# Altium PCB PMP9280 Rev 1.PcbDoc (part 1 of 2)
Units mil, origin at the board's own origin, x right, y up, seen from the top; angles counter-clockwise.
Board outline 4050 x 2360 mil, 4 copper layers (Top Layer, MidLayer1, MidLayer2, Bottom Layer), stack 61.2 mil thick; 80 components, 27 nets, 139 pads, 275 vias.
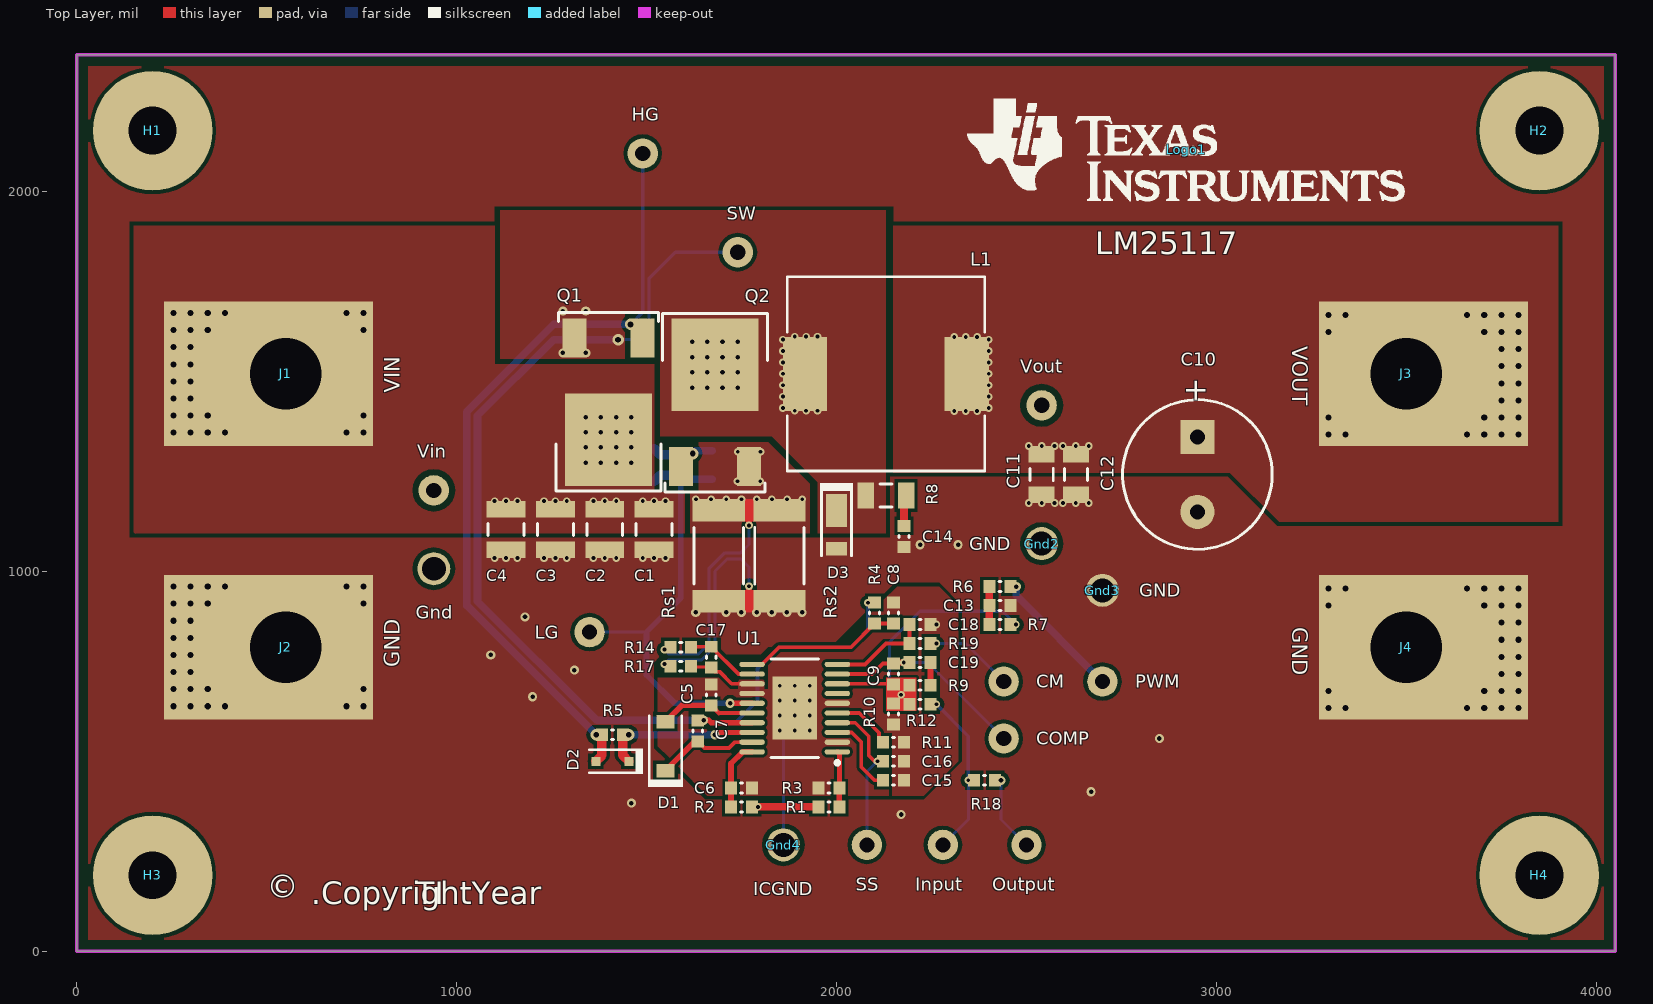
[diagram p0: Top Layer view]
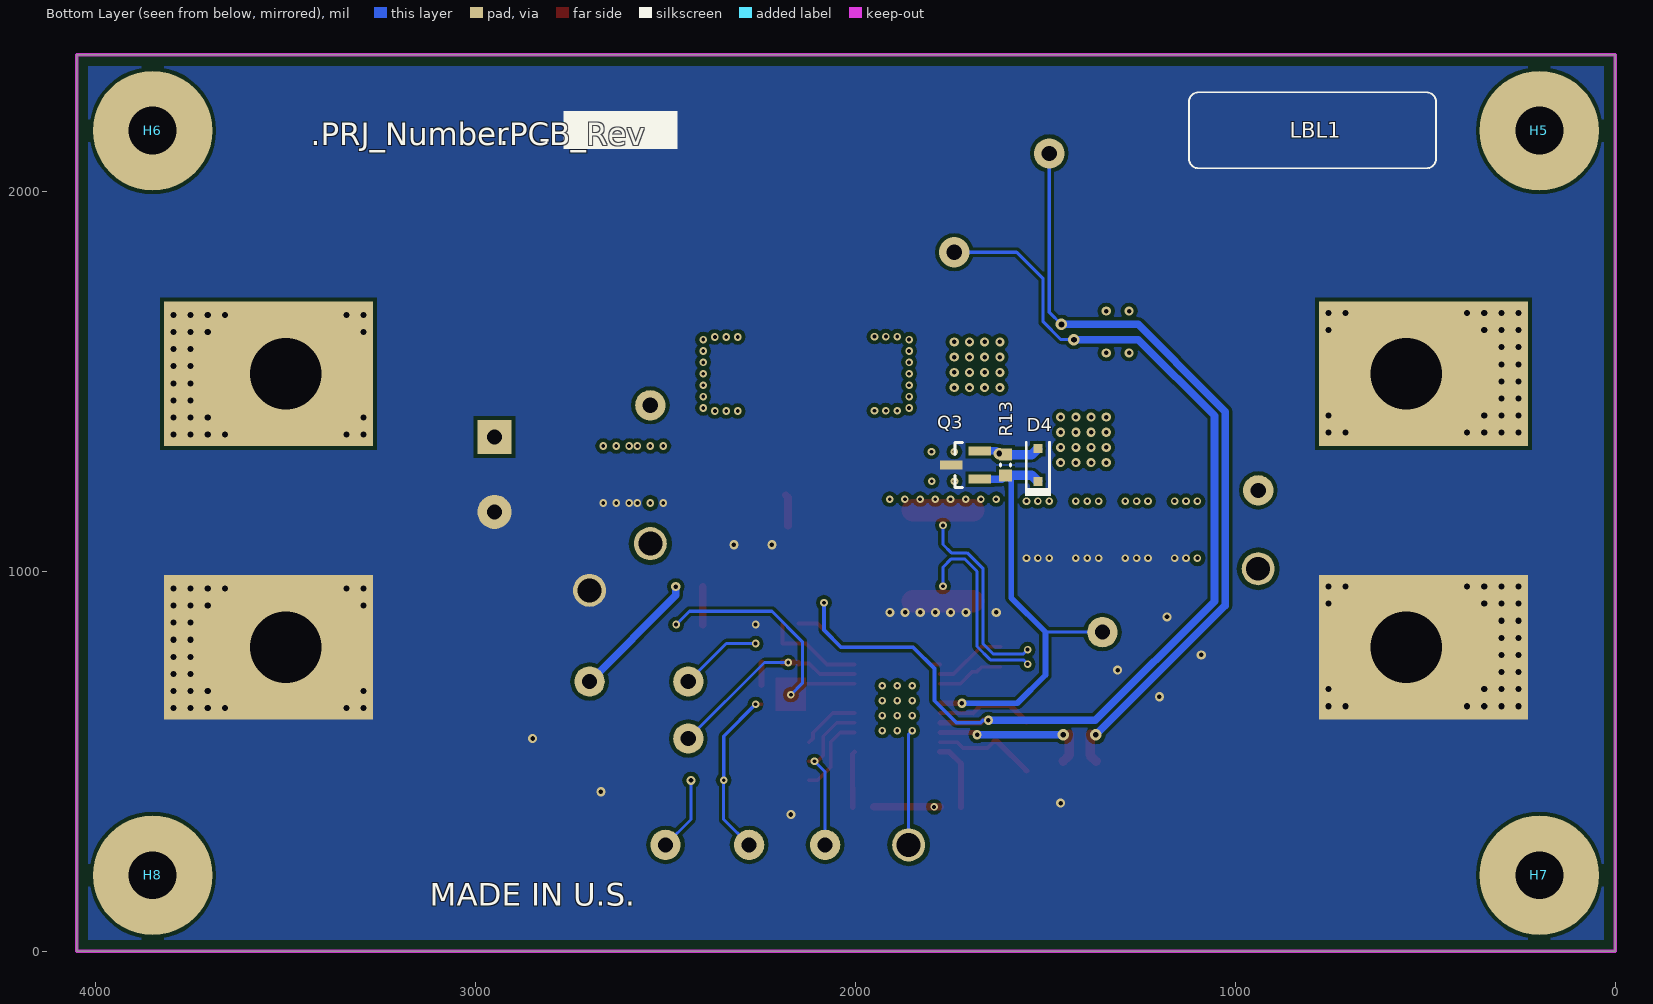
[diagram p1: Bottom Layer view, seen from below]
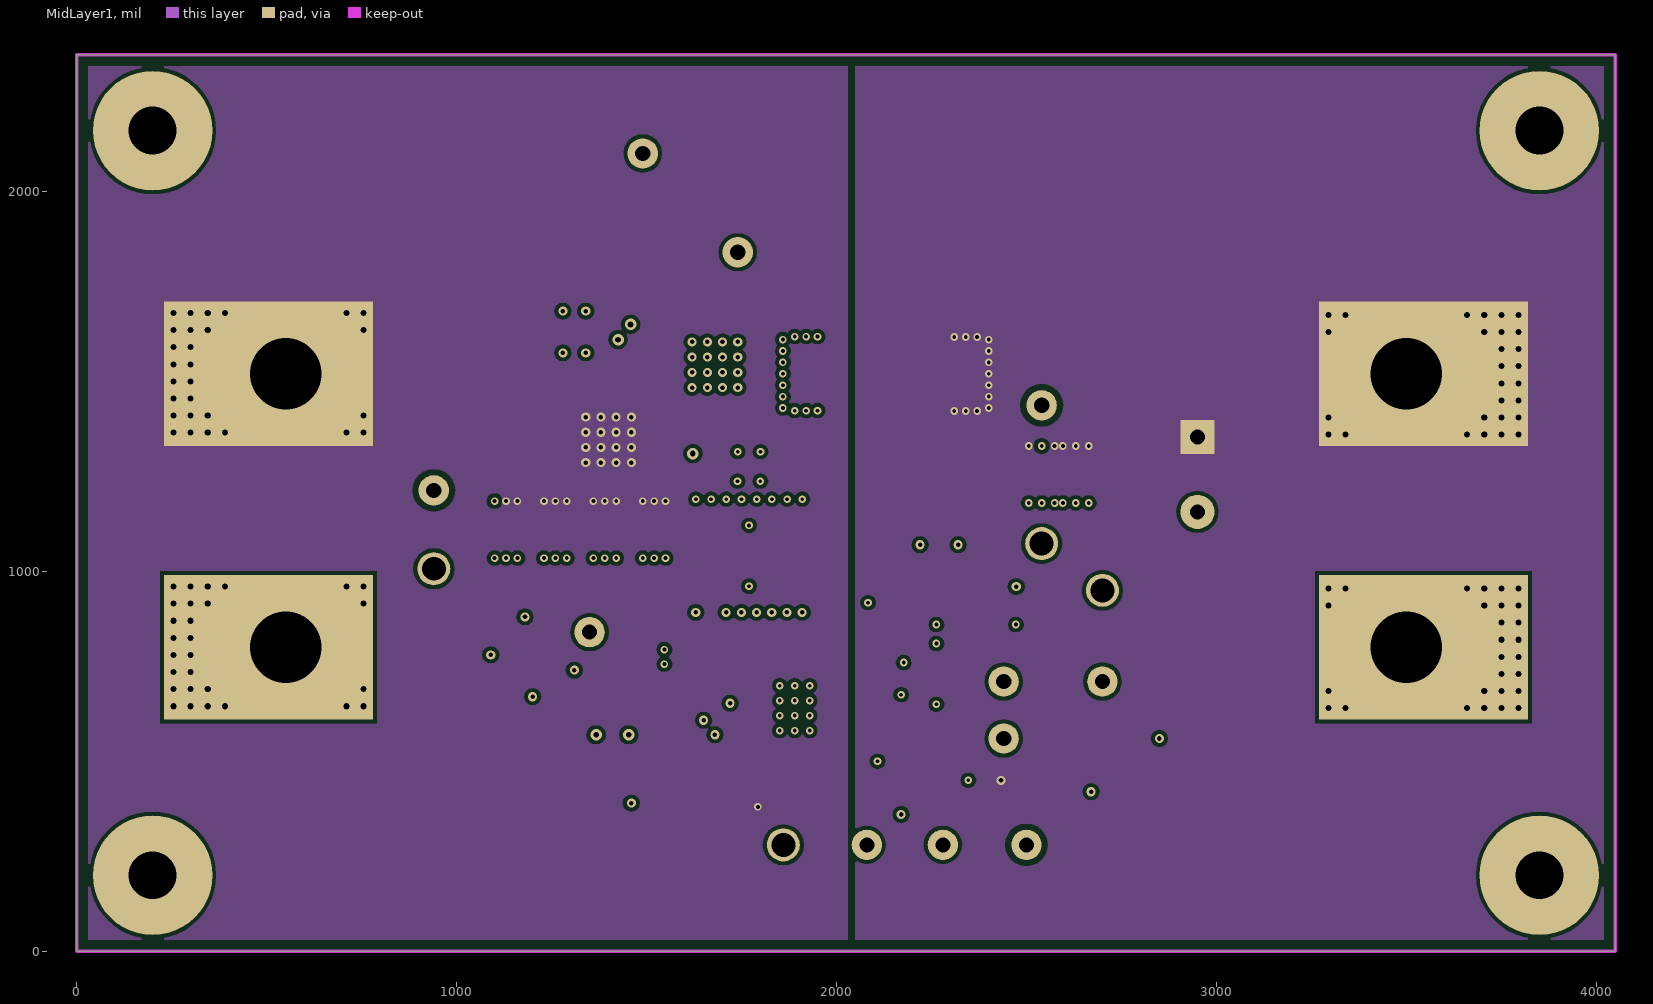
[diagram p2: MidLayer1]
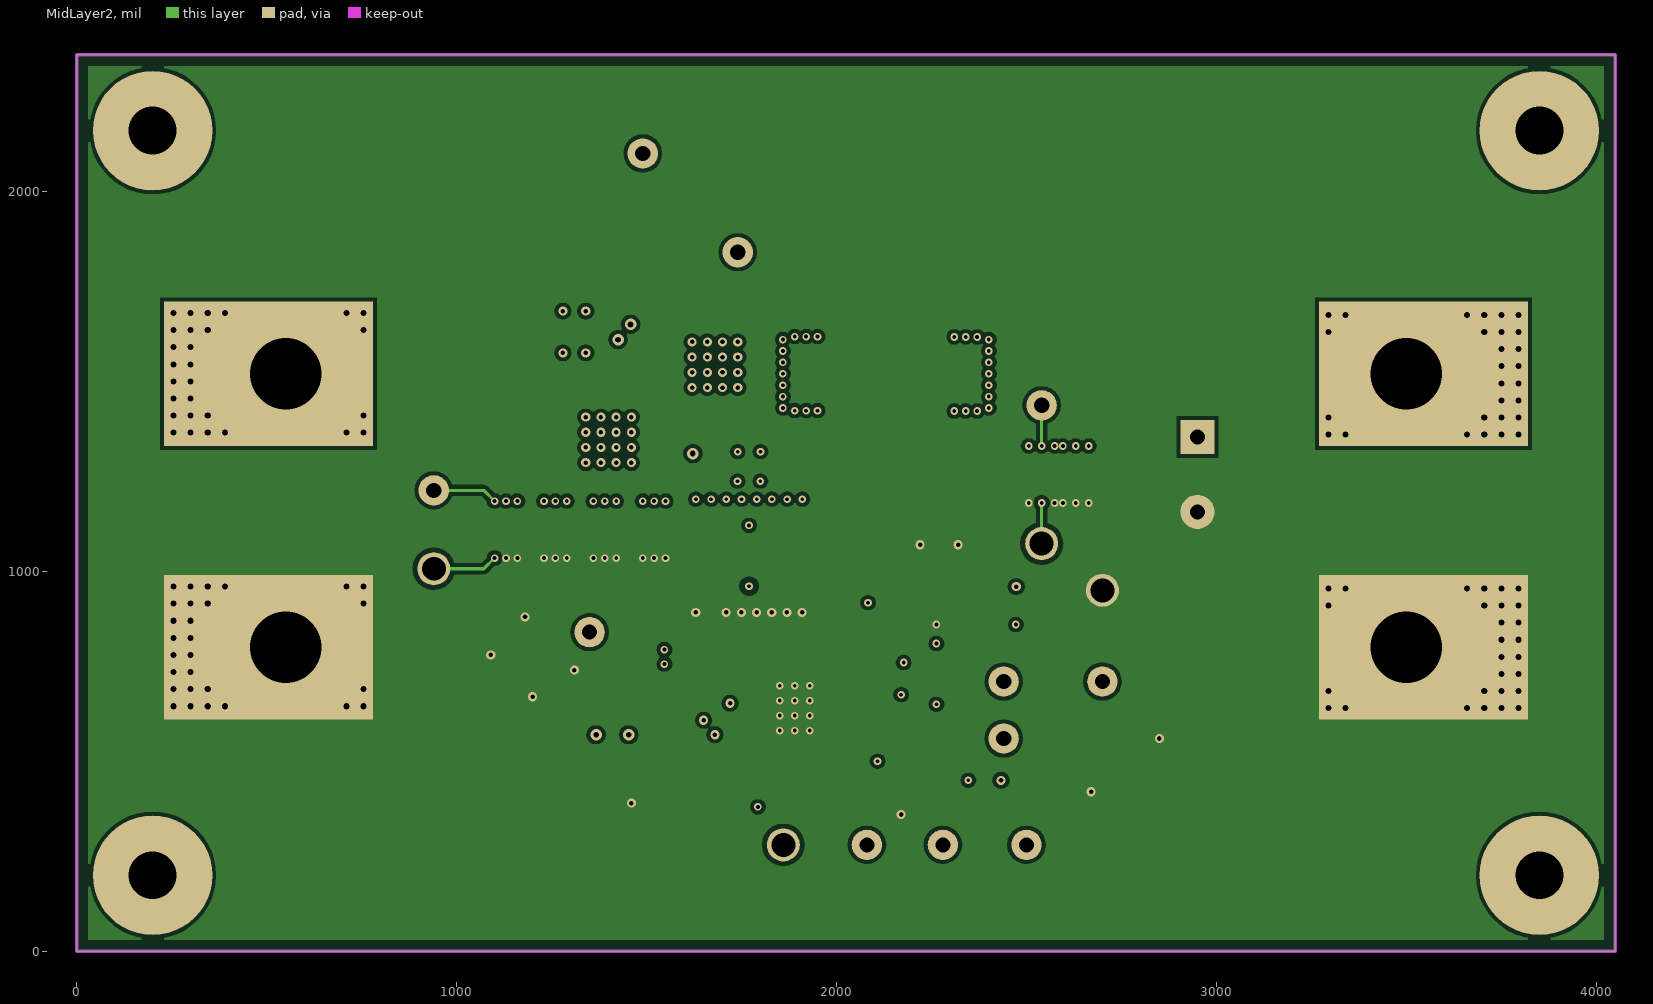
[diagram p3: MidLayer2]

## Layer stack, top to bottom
Top Solder: solder mask 0.4, Solder Resist, Dk 3.5
Top Layer: signal copper 1.4
Dielectric1: core 12.6, FR-4, Dk 4.8
MidLayer1: signal copper 1.4
Dielectric2: prepreg 30.4, FR-4, Dk 4.8
MidLayer2: signal copper 1.4
Dielectric3: core 12.6, FR-4, Dk 4.8
Bottom Layer: signal copper 1.4
Bottom Solder: solder mask 0.4, Solder Resist, Dk 3.5

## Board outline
0,0 0,2360 4050,2360 4050,0

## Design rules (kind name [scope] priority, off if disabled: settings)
AcuteAngle [All] p1: minimum=4.50000000000000E+0001 checktracksonly=FALSE
AssemblyTestPointUsage [All] p1: valid=2
Clearance Clearance_Poly_1 [InNet('GND') vs OnLayer('Top Layer')] p1: gap=8 ignorepadtopadclearanceinfootprint=FALSE except(0: Arc-Hole Track-Hole SMDPad-Hole THPad-Hole Via-Hole Fill-Hole Poly-Hole Region-Hole Text-Hole)
Clearance Clearance_Poly_2 [InNet('GND') vs OnLayer('Bottom Layer')] p2: gap=8 ignorepadtopadclearanceinfootprint=FALSE except(0: Arc-Hole Track-Hole SMDPad-Hole THPad-Hole Via-Hole Fill-Hole Poly-Hole Region-Hole Text-Hole)
Clearance Clearance_BoardEdge_MountingHoles [OnCopper and InComponentClass('Mounting Holes') vs IsKeepOut] p3: gap=20 ignorepadtopadclearanceinfootprint=FALSE except(0: Arc-Hole Track-Hole SMDPad-Hole THPad-Hole Via-Hole Fill-Hole Poly-Hole Region-Hole Text-Hole)
Clearance Clearance_BoardEdge_Poly [OnCopper and InPoly vs IsKeepOut] p4: gap=25 ignorepadtopadclearanceinfootprint=FALSE except(0: Arc-Hole Track-Hole SMDPad-Hole THPad-Hole Via-Hole Fill-Hole Poly-Hole Region-Hole Text-Hole)
Clearance Clearance_BoardEdge [OnCopper and Not InComponentClass('Logo') and not InComponentClass('FiducialMark') and not InRegion(1000,500,4000,800) and Not IsKeepout vs IsKeepOut] p5: gap=35 ignorepadtopadclearanceinfootprint=FALSE except(0: Arc-Hole Track-Hole SMDPad-Hole THPad-Hole Via-Hole Fill-Hole Poly-Hole Region-Hole Text-Hole)
Clearance Clearance_Poly [InPolygon] p6: gap=10 ignorepadtopadclearanceinfootprint=FALSE except(0: Arc-Hole Track-Hole SMDPad-Hole THPad-Hole Via-Hole Fill-Hole Poly-Hole Region-Hole Text-Hole)
Clearance [All] p7: gap=8 ignorepadtopadclearanceinfootprint=FALSE except(0: Arc-Hole Track-Hole SMDPad-Hole THPad-Hole Via-Hole Fill-Hole Poly-Hole Region-Hole Text-Hole)
ComponentClearance ComponentClearance_Logo [InComponentClass('Logo')] p1: gap=50 collisioncheckmode=3 verticalgap=10 showdistances=FALSE
ComponentClearance ComponentClearance_ScrewToNut [(HasFootprint('NY PMS 440 0025 PH')) vs (HasFootprint('Keystone_1902C'))] p2: gap=5 collisioncheckmode=3 verticalgap=10 showdistances=FALSE
ComponentClearance ComponentClearance_MountingHoles [InComponentClass('Mounting Holes')] p3: gap=250 collisioncheckmode=3 verticalgap=100000 showdistances=FALSE
ComponentClearance ComponentClearance_SmallPassives [HasFootprint('0201*') or HasFootprint('0402*') or HasFootprint('0508') or HasFootprint('0603*') or HasFootprint('0612') or HasFootprint('0805*') or HasFootprint('0815*') or HasFootprint('0830*') or HasFootprint('1206*') or HasFootprint('1210*') or HasFootprint('1808*') or HasFootprint('1812*') or HasFootprint('1825*') or HasFootprint('2010*') or HasFootprint('2220*') or HasFootprint('2225*') or HasFootprint('2512*') or HasFootprint('2728*') or HasFootprint('3518*') vs HasFootprint('0201*') or HasFootprint('0402*') or HasFootprint('0508') or HasFootprint('0603*') or HasFootprint('0612') or HasFootprint('0805*') or HasFootprint('0815*') or HasFootprint('0830*') or HasFootprint('1206*') or HasFootprint('1210*') or HasFootprint('1808*') or HasFootprint('1812*') or HasFootprint('1825*') or HasFootprint('2010*') or HasFootprint('2220*') or HasFootprint('2225*') or HasFootprint('2512*') or HasFootprint('2728*') or HasFootprint('3518*')] p4: gap=10 collisioncheckmode=3 verticalgap=10 showdistances=FALSE
ComponentClearance ComponentClearance_THtoSMT [IsThruComponent vs IsSMTComponent] p5: gap=30 collisioncheckmode=3 verticalgap=30 showdistances=FALSE
ComponentClearance ComponentClearance_THtoTH [IsThruComponent vs IsThruComponent] p6: gap=50 collisioncheckmode=3 verticalgap=30 showdistances=FALSE
ComponentClearance [All] p7: gap=20 collisioncheckmode=3 verticalgap=10 showdistances=FALSE
DiffPairsRouting [All] p1: maxlimit=100 minlimit=10 mostfreqgap=10 toplayer_minwidth=15 toplayer_maxwidth=15 toplayer_prefwidth=15 midlayer1_minwidth=15 midlayer1_maxwidth=15 midlayer1_prefwidth=15 midlayer2_minwidth=15 midlayer2_maxwidth=15 midlayer2_prefwidth=15 bottomlayer_minwidth=15 bottomlayer_maxwidth=15 bottomlayer_prefwidth=15 maxuncoupledlength=1000
FabricationTestPointUsage TestPointUsage [All] p1: valid=2 allowmultiple=FALSE
FabricationTestpoint Testpoint [All] p1: side=3 testpointundercomponent=TRUE minsize=40 maxsize=100 preferedsize=60 minholesize=0 maxholesize=40 preferedholesize=32 testpointgrid=1 allowsidetop=TRUE allowsidebottom=TRUE usegrid=TRUE gridtolerance=0.01
FanoutControl Fanout_LCC [IsLCC] p1: bgadir=Out bgaviamode=Centered fanoutstyle=Auto fanoutdirection=Alternating viagrid=1 // Fanout_LCC (Default Rule)
FanoutControl Fanout_BGA [IsBGA] p2: bgadir=Out bgaviamode=Centered fanoutstyle=Auto fanoutdirection=Alternating viagrid=1 // Fanout_BGA (Default Rule)
FanoutControl Fanout_Default [All] p4: bgadir=Out bgaviamode=Centered fanoutstyle=Auto fanoutdirection=Alternating viagrid=1 // Fanout_Default (Default Rule)
FanoutControl Fanout_Small [(CompPinCount < 5)] p5: bgadir=Out bgaviamode=Centered fanoutstyle=Auto fanoutdirection=OutThenIn viagrid=1 // Fanout_Small (Default Rule)
HoleSize [All] p1: absolutevalues=TRUE maxlimit=251 minlimit=8 maxpercent=80.000 minpercent=20.000
MinimumAnnularRing [All] p1: minimumring=9
MinimumSolderMaskSliver MinimumSolderMaskSliver_Logo [InComponentClass('Logo') vs InComponentClass('Logo')] p1: minsoldermaskwidth=0.7
MinimumSolderMaskSliver [All] p2: minsoldermaskwidth=4
PlaneClearance [All] p1: clearance=15
PlaneConnect [All] p1: planeconnectstyle=Relief reliefexpansion=10 reliefentries=4 reliefconductorwidth=10 reliefairgap=10
PolygonConnect [All] p1: connectstyle=Direct reliefconductorwidth=10 reliefentries=4 polygonreliefangle="90 Angle" airgapwidth=10
RoutingVias [All] p1: holewidth=16 width=34 viastyle="Through Hole" minholewidth=8 minwidth=26 maxholewidth=40 maxwidth=65
SMDToCorner [All] p1: distance=30000
SilkToSilkClearance [All] p1: silktosilkclearance=5
SilkToSolderMaskClearance SilkscreenOverComponentPads [IsPad] p1: minsilkscreentomaskgap=5 clearancetoexposedcopper=TRUE
SolderMaskExpansion [All] p1: expansion=3
Width [All] p1: maxlimit=100 minlimit=6 preferedwidth=10 checkconnectedcopper=TRUE
15 further rules are at their usual default settings.

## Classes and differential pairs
component class "PMP9280 Rev 7 schematic": C1 C2 C3 C4 C5 C6 C7 C8 C9 C10 C11 C12 C13 C14 C15 C16 C17 C18 C19 CM COMP D1 D2 D3 D4 Gnd Gnd2 Gnd3 Gnd4 HG Input J1 J2 J3 J4 L1 LG Output PWM Q1 Q2 Q3 R1 R2 R3 R4 R5 R6 R7 R8 R9 R10 R11 R12 R13 R14 R17 R18 R19 Rs1 Rs2 SS SW U1 Vin Vout
component class Label: LBL1
component class AssemblyNote: ZZ1 ZZ2 ZZ3 ZZ4
component class PMP9280_Hardware_ANSI-B: H1 H2 H3 H4 H5 H6 H7 H8 LBL1 Logo1 ZZ1 ZZ2 ZZ3 ZZ4
component class Logo: Logo1
component class "Mounting Holes": H1 H2 H3 H4
differential pair HO: +HO_P -HO_N

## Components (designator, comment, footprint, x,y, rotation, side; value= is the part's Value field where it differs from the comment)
C1 "GRM32ER71H106KA12L" 1210L 1520,1110 r270 top
C2 "GRM32ER71H106KA12L" 1210L 1390,1110 r270 top
C3 "GRM32ER71H106KA12L" 1210L 1260,1110 r270 top
C4 "GRM32ER71H106KA12L" 1210L 1130,1110 r270 top
C5 "GRM188R61C475KAAJ" 0603L 1670,675 r90 top
C6 "GRM188R71E105KA12D" 0603L 1750,430 r0 top
C7 "GRM188R71E105KA12D" 0603L 1635,580 r90 top
C8 "GRM1885C1H821JA01D" 0603L 2150,890 r90 top
C9 "GRM1885C1H101JA01D" 0603L 2150,730 r270 top
C10 "EEU-FR1V681" CAPPR5-10X20 2950,1255 r270 top
C11 "C1206C105K3RACTU" 1206L 2540,1255 r270 top
C12 "C1206C105K3RACTU" 1206L 2630,1255 r270 top
C13 "GRM188R60J106ME47D" 0603L 2430,910 r0 top
C14 "06031C222KAT2A" 0603L 2177.56,1092 r270 top
C15 "GRM188R71C474KA88D" 0603L 2150,450 r0 top
C16 "GCM188R71H104KA57B" 0603L 2150,500 r0 top
C17 "GRM1885C1H101JA01D" 0603L 1670,773.98 r270 top
C18 "GRM188R61H103KA01D" 0603L 2220,860 r0 top
C19 "GRM188R61H103KA01D" 0603L 2220,760 r0 top
CM "5000" Keystone5000 2440,710 r90 top
COMP "5002" Keystone5002 2440,560 r90 top
D1 "RB160M-90TR" SOD-123 1550,540 r90 top
D2 "DNP" sod-323 1410,500 r180 top
D3 "DNP" powerDI123 2000,1110 r270 top
D4 "DNP" sod-323 1520,1280 r90 bottom
Gnd "5011" Keystone5011 940,1006.85 r90 top
Gnd2 "GND" Keystone5011 2540,1073 r270 top
Gnd3 "GND" Keystone5011 2700,950 r90 top
Gnd4 "ICGND" Keystone5011 1860,280 r270 top
H1 "NY PMS 440 0025 PH" "NY PMS 440 0025 PH" 200,2160 r0 top
H2 "NY PMS 440 0025 PH" "NY PMS 440 0025 PH" 3850,2160 r0 top
H3 "NY PMS 440 0025 PH" "NY PMS 440 0025 PH" 200,200 r0 top
H4 "NY PMS 440 0025 PH" "NY PMS 440 0025 PH" 3850,200 r0 top
H5 "1902C" Keystone_1902C 200,2160 r180 bottom
H6 "1902C" Keystone_1902C 3850,2160 r180 bottom
H7 "1902C" Keystone_1902C 199.77,200.01 r180 bottom
H8 "1902C" Keystone_1902C 3850,200 r180 bottom
HG "5002" Keystone5002 1490,2100 r90 top
Input "5000" Keystone5000 2280,280 r90 top
J1 "VIN" CB35-36-CY 550,1520 r0 top
J2 "GND" CB35-36-CY 550,800 r0 top
J3 "VOUT" CB35-36-CY 3500,1520 r180 top
J4 "GND" CB35-36-CY 3500,800 r180 top
L1 "Vishay, IHLP6767GZ-01 6.8uH" IHLP-5050FD 2130,1520 r0 top
LBL1 "Size: 0.65\" x 0.20 \"" Label_650x200 797,2161 r180 bottom
LG "5002" Keystone5002 1350,840 r90 top
Logo1 "Texas Instruments" TI_Stacked_Overlay_Medium 2920,2110 r0 top
Output "5000" Keystone5000 2500,280 r90 top
PWM "PWM Input (0 to 5V PWM at 200kHz)" Keystone5000 2700,710 r90 top
Q1 "STD35NF06LT4" DPAK 1400,1480 r270 top
Q2 "STD35NF06LT4" DPAK 1680,1410 r90 top
Q3 "DNP" SOT-23 1710,1280 r0 bottom
R1 "CRCW060349K9FKEA" 0603L 1980,380 r180 top
R2 "CRCW06033R32FKEA" 0603L 1750,380 r180 top
R3 "CRCW06035K36FKEA" 0603L 1980,430.01 r0 top
R4 "CRCW0603137KFKEA" 0603L 2100,890 r90 top
R5 "CRCW06030000Z0EA" 0603L 1410,570 r180 top
R6 "CRCW06032K00FKEA" 0603L 2430,960 r180 top
R7 "CRCW06032K00FKEA" 0603L 2430,860 r180 top
R8 "CRCW12061R00JNEA" 1206L 2130,1200 r180 top
R9 "RT0603DRE0729K1L" 0603L 2220,700 r0 top
R10 "CRCW06031K00JNEA" 0603L 2150,625 r90 top
R11 "CRCW060324K9FKEA" 0603L 2150,550 r180 top
R12 "CRCW060315K0FKEA" 0603L 2220,650 r180 top
R13 "CRCW06030000Z0EA" 0603L 1605,1280 r90 bottom
R14 "CRCW0603100RFKEA" 0603L 1590,800 r180 top
R17 "CRCW0603100RFKEA" 0603L 1590,750 r0 top
R18 "CRCW06030000Z0EA" 0603L 2390,450 r180 top
R19 "CRCW06031K00JNEA" 0603L 2220,810 r0 top
Rs1 "ERJ-M1WSF4M0U" 2512M 1689.76,1040.92 r90 top
Rs2 "ERJ-M1WSF4M0U" 2512M 1849.76,1040.92 r90 top
SS "5002" Keystone5002 2080,280 r90 top
SW "5002" Keystone5002 1740,1840 r0 top
U1 "LM25117PMH/NOPB" MXA20A_N 1890,640 r180 top
Vin "5000" Keystone5000 940,1213.15 r90 top
Vout "Vout 13V out max @ 15A" Keystone5000 2540,1437 r270 top
ZZ1 "This Assembly Note is for PCB labels only" AssemblyNoteLabel -375,3378 r0 top
ZZ2 "These assemblies are ESD sensitive, ESD precautions shall be observed." AssemblyNote -375,3269.11 r0 top
ZZ3 "These assemblies must be clean and free from flux and all contaminants. Use of no clean flux is not acceptable." AssemblyNote -375,3180.56 r0 top
ZZ4 "These assemblies must comply with workmanship standards IPC-A-610 Class 2., unless otherwise specified." AssemblyNote -375,3092 r0 top

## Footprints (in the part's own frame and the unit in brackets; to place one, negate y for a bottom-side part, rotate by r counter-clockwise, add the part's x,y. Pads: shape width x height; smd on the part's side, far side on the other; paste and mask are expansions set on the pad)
0603L [mm] "0603 from SM-752 data"
  rect 0.8x0.85 smd: 1(-0.7,0) 2(0.7,0)
  silkscreen extent -0.07,-0.33 0.07,0.33, body extent -0.87,-0.47 0.87,0.47, height 0.85
1206L [mm] "1206 from SM-752 data"
  rect 1.1x1.75 smd: 1(-1.35,0) 2(1.35,0)
  silkscreen extent -0.4,-0.77 0.4,0.77, body extent -1.7,-0.9 1.7,0.9, height 1.35
1210L [mm] "1210 from SM-752 data"
  rect 1.1x2.6 smd: 1(-1.35,0) 2(1.35,0)
  silkscreen extent -0.4,-1.2 0.4,1.2, body extent -1.7,-1.35 1.7,1.35, height 1.35
2512M [mm] "Chip Resistor, Body 6.3x3.2mm, IPC Low Density"
  rect 1.5x3.5 smd: 1(-3.05,0) 2(3.05,0)
  silkscreen extent -1.9,-1.65 1.9,1.65, body extent -3.22,-1.67 3.22,1.67, height 0.71
AssemblyNote [mil] "Assembly Note"
AssemblyNoteLabel [mil] "Assembly Note for PCB Labels"
CAPPR5-10X20 [mil] "Capacitor, Electrolytic, Radial; Body 10 x 20 mm (Dia.xH typ); Pin Spacing 5 mm (typ)"
  rect 90x90 hole 40: 1(-98.43,0)
  round 90 hole 40: 2(98.43,0)
  silkscreen extent -197,-197 197,197, body extent -197,-197 197,197, height 866
CB35-36-CY [mil] "Terminal 50A Lug"
  rect 550x380 hole 188 copper offset -45,0 paste-190: 1(0,0)
  body extent -960,-189 230,191, height 614
DPAK [mm] "D-PAK, 3-Pads, Body 6.22x6.73mm (max), TO-252AA using nominal STEP model"
  rect 2.6x1.6 smd: 1(-3.4,2.28) 3(-3.4,-2.28)
  rect 6.2x5.8 smd paste-2.9: 4(3.4,0)
  silkscreen extent -5.1,-3.5 6.83,3.5, body extent -3.86,-3.29 5.84,3.29, height 2.48
IHLP-5050FD [mm] "Vishay Dale recommended land pattern.  Document 34123 rev 18-Sep-09"
  rect 2.945x4.95 smd: 1(-5.407,0) 2(5.407,0)
  silkscreen extent -6.6,-6.5 6.6,6.5, body extent -6.86,-6.45 6.86,6.45, height 6.5
Keystone5000 [mil] "For Keystone 500x miniature loop terminals"
  round 80 hole 40: 1(0,0)
  body extent -49,-49 49,49, height 182
Keystone5002 [mil] "For Keystone 500x miniature loop terminals"
  round 80 hole 40: 1(0,0)
  body extent -49,-49 49,49, height 182
Keystone5011 [mil] "Keystone Multipurpose loops"
  round 87 hole 63: 1(0,0)
  body extent -63,-63 63,62, height 319
Keystone_1902C [mil] "Hex Standoff, 4-40 threaded, nylon"
  body extent -145,-126 146,126, height 501
Label_650x200 [mil] "Thermal Transfer Label"
  silkscreen extent -325,-100 325,100, body extent -325,-100 325,100, height 1
MXA20A_N [mm] "TSOP, 20-Leads, Body 6.5x4.4mm, Pitch 0.65mm, Exposed Pad, IPC Medium Density"
  oval 1.7x0.35 smd: 1(-2.85,2.925) 2(-2.85,2.275) 3(-2.85,1.625) 4(-2.85,0.975) 5(-2.85,0.325) 6(-2.85,-0.325) 7(-2.85,-0.975) 8(-2.85,-1.625) 9(-2.85,-2.275) 10(-2.85,-2.925) 11(2.85,-2.925) 12(2.85,-2.275) 13(2.85,-1.625) 14(2.85,-0.975) 15(2.85,-0.325) 16(2.85,0.325) 17(2.85,0.975) 18(2.85,1.625) 19(2.85,2.275) 20(2.85,2.925)
  rect 3x4.2 smd: 21(0,0)
  silkscreen extent -2.98,-3.3 1.6,3.77, body extent -2.25,-3.3 2.25,3.3, height 1.1
"NY PMS 440 0025 PH" [mm] "4-40 nylon screw and mounting hole"
  round 8 hole 3.2: ""(0,0)
  body extent -3.3,-3.3 3.3,3.3, height 2.69
powerDI123 [mm] "Diodes Inc recommended land pattern, document number DS30628 Rev. 6-2"
  rect 2.2x1.4 smd: 1(-1.275,0)
  rect 0.9x1.4 smd: 2(1.275,0)
  silkscreen extent -3.1,-1.09 1.76,1.09, body extent -2.37,-0.96 1.53,0.97, height 1
SOD-123 [mm] "On Semi recommended land pattern"
  rect 0.915x1.22 smd: 1(-1.637,0) 2(1.637,0)
  silkscreen extent -2.74,-1.17 2.03,1.17, body extent -1.93,-0.9 1.93,0.9, height 1.35
sod-323 [mm] "NXP recommended land pattern"
  rect 0.6x0.6 smd paste-0.05: 1(-1.1,0) 2(1.1,0)
  silkscreen extent -2.06,-0.86 1.53,0.86, body extent -1.3,-0.67 1.3,0.68, height 1.1
SOT-23 [mm] "SOT23, 3-Leads, Body 2.9x1.3mm, Pitch 0.95mm, Lead Span 2.5mm, IPC Medium Density"
  rect 1.5x0.6 smd: 1(-0.95,0.95) 2(-0.95,-0.95) 3(0.95,0)
  silkscreen extent 0.2,-1.5 0.7,1.5, body extent -1.16,-1.45 1.21,1.45, height 1
TI_Stacked_Overlay_Medium [mil]
  silkscreen extent -576,-136 576,134

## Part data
C1 C2 C3 C4: "CAP, CERM, 10uF, 50V, +/-10%, X7R, 1210"
C5: "CAP, CERM, 4.7uF, 16V, +/-10%, X5R, 0603"
C6 C7: "CAP, CERM, 1uF, 25V, +/-10%, X7R, 0603"
C8: "CAP, CERM, 820pF, 50V, +/-5%, C0G/NP0, 0603"
C9 C17: "CAP, CERM, 100pF, 50V, +/-5%, C0G/NP0, 0603"
C10: "CAP, AL, 560uF, 35V, +/-20%, TH"
C11 C12: "CAP, CERM, 1uF, 25V, +/-10%, X7R, 1206"
C13: "CAP, CERM, 10uF, 6.3V, +/-20%, X5R, 0603"
C14: "CAP, CERM, 2200pF, 100V, +/-10%, X7R, 0603"
C15: "CAP, CERM, 0.47uF, 16V, +/-10%, X7R, 0603"
C16: "CAP, CERM, 0.1uF, 50V, +/-10%, X7R, 0603"
C18 C19: "CAP, CERM, 0.01uF, 50V, +/-10%, X5R, 0603"
CM Input Output Vin: "Test Point, Miniature, Red, TH"
COMP HG LG SS SW: "Test Point, Miniature, White, TH"
D1: "Diode, Schottky, 90V, 1A, SOD-123"
D2 D4: library part BAT42WS-7-F, "Diode, Schottky, 30V, 0.2A, SOD-323"
D3: library part DFLS1100-7, "Diode, Schottky, 100V, 1A, PowerDI123"
Gnd: "Test Point, TH, Multipurpose, Black"
Gnd2 Gnd3 Gnd4: library part 5011, "Test Point, TH, Multipurpose, Black"
H1 H2 H3 H4: "Machine Screw, Round, #4-40 x 1/4, Nylon, Philips panhead"
H5 H6 H7 H8: "Standoff, Hex, 0.5\"L #4-40 Nylon"
J1 J2 J3 J4: library part CB35-36-CY, "Terminal 50A Lug"
L1: library part IHLP5050FDER6R8M01, "Inductor, Shielded, Powdered Iron, 6.8uH, 11.5A, 14 ohm, SMD"
LBL1: library part THT-14-423-10, "Thermal Transfer Printable Labels, 0.650\" W x 0.200\" H - 10,000 per roll"
Logo1: library part TI_Logo, "Texas Instrument Corporate Signature"
PWM Vout: library part 5000, "Test Point, Miniature, Red, TH"
Q1 Q2: library part STD13NM60N, "MOSFET N-CH 60V 35A DPAK"
Q3: library part "MMBT3906, Fairchild Semiconductor", "Transistor, PNP, 40V, 0.2A, SOT-23"
R1: "RES, 49.9k ohm, 1%, 0.1W, 0603"
R2: "RES, 3.32 ohm, 1%, 0.1W, 0603"
R3: "RES, 5.36k ohm, 1%, 0.1W, 0603"
R4: "RES, 137k ohm, 1%, 0.1W, 0603"
R5 R13 R18: "RES, 0 ohm, 5%, 0.1W, 0603"
R6 R7: "RES, 2.00k ohm, 1%, 0.1W, 0603"
R8: "RES, 1.0 ohm, 5%, 0.25W, 1206"
R9: "RES, 29.1k ohm, 0.5%, 0.1W, 0603"
R10 R19: "RES, 1.0k ohm, 5%, 0.1W, 0603"
R11: "RES, 24.9k ohm, 1%, 0.1W, 0603"
R12: "RES, 15.0k ohm, 1%, 0.1W, 0603"
R14 R17: "RES, 100 ohm, 1%, 0.1W, 0603"
Rs1 Rs2: "RES, 0.004 ohm, 1%, 1W, 2512"
U1: library part LM5117PMH/NOPB, "Wide Voltage Range Buck-Boost Controller, 20-pin TSSOP-EP, Pb-Free"
ZZ1: library part AssemblyNoteLabel
ZZ2 ZZ3 ZZ4: library part AssemblyNote

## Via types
v1: diameter 32, hole 16, Top Layer to Bottom Layer, 112 vias
v2: diameter 20, hole 10, Top Layer to Bottom Layer, tented both sides, 88 vias
v3: diameter 24, hole 12, Top Layer to Bottom Layer, tented both sides, 58 vias
v4: diameter 20, hole 10, Top Layer to Bottom Layer, 12 vias
v5: diameter 30, hole 15, Top Layer to Bottom Layer, tented both sides, 5 vias

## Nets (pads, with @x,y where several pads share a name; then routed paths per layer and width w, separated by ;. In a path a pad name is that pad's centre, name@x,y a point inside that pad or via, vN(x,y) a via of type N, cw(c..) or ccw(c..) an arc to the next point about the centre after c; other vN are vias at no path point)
CM: C18.1 R19.1 U1.10 | length 263
  Top Layer w10: U1.10@2002.2,755.16 2075.16,755.16 2130,810 R19.1@2192.44,810 C18.1@2192.44,860
COMP: C9.1 C19.1 COMP.1 U1.9 | length 548.6
  Top Layer w10: U1.9@2002.2,729.57 2094.01,729.57 2122,757.56 C9.1@2150,757.56
  Top Layer w15: C9.1@2150,757.56 2152.44,760 C19.1@2192.44,760
  Bottom Layer w8: v2(2177,760) 2239.71,760 COMP.1@2439.88,559.82
CS: C17.1 R14.1 U1.12 | length 190
  Top Layer w10: R14.1@1617.56,801.54 C17.1@1670,801.54 1741.97,729.57 U1.12@1777.8,729.57
FB: C9.2 R7.1 R9.1 R10.2 R12.2 U1.8 | length 680.4
  Top Layer w10: U1.8@2002.2,703.98 2148.46,703.98 C9.2@2150,702.44
  Bottom Layer w8: v2(2170,675.27) 2140,705.27 2140,815 2220,895 2437.2,895 v2(2472.2,860)
GND: C1.2 C2.2 C3.2 C4.2 C5.2 C6.2 C8.2 C10.2 C11.2 C12.2 C13.2 C14.2 C15.2 C16.2 C17.2 C18.2 D3.2 Gnd2.1 Gnd3.1 Gnd4.1 Gnd.1 J2.1 J4.1 Q3.3 R3.1 R10.1 R11.1 R17.1 R17.2 Rs1.1 Rs2.1 U1.2 U1.6 U1.13 U1.14 U1.21 | length 1473.9
  Top Layer w8: R17.2@1617.56,748.39 C17.2@1670,748.39
  Top Layer w10: C17.2@1670,746.42 1680.42,736 1692,736 1724.02,703.98 U1.13@1777.8,703.98
  Top Layer w15: 1769.76,920.84 v2(1769.76,960.92)
  Top Layer w59: Rs1.1@1689.76,920.84 1769.76,920.84 Rs2.1@1849.76,920.84
  MidLayer2 w8: Gnd.1@940,1006.85 1071.85,1006.85 v2(1100,1035) ; Gnd2.1@2540,1073 v2(2540,1180)
  Bottom Layer w8: v2(1547,756) 1558,767 1645,767 1680,802 1680,1000 1712.92,1032.92 1747.76,1032.92 1769.76,1010.92 v2(1769.76,960.92) ; v4(1850.63,580.94) 1860,571.57 Gnd4.1@1860,280
  other v1: 3295,640 3340,640 3660,640 3705,640 3750,640 3795,640 255,645 300,645 345,645 390,645 710,645 755,645 3295,685 3705,685 3750,685 3795,685 255,690 300,690 345,690 755,690 3750,730 3795,730 255,735 300,735 3750,775 3795,775 255,780 300,780 3750,820 3795,820 255,825 300,825 3750,865 3795,865 255,870 300,870 3295,910 3705,910 3750,910 3795,910 255,915 300,915 345,915 755,915 3295,955 3340,955 3660,955 3705,955 3750,955 3795,955 255,960 300,960 345,960 390,960 710,960 755,960
  other v2: 2263,860 1130,1035 1160,1035 1230,1035 1260,1035 1290,1035 1360,1035 1390,1035 1420,1035 1490,1035 1520,1035 1550,1035 2506,1180 2574,1180 2596,1180 2630,1180 2664,1180
  other v3: 2170,360 1460,390 2670,420 2850,560 1200,670 1310,740 1090,780 1180,880 1629.53,891.84 1709.53,891.84 1749.53,891.84 1789.53,891.84 1829.53,891.84 1869.53,891.84 1909.53,891.84 2220,1070 2320,1070
  other v4: 1890,580.94 1929.37,580.94 1850.63,620.31 1890,620.31 1929.37,620.31 1850.63,659.68 1890,659.68 1929.37,659.68 1850.63,699.06 1890,699.06 1929.37,699.06
HB: C7.1 D1.1 U1.19 | length 273.3
  Top Layer w10: C7.1@1635,552.44 1652.44,535 1717,535 1732.43,550.43 U1.19@1777.8,550.43
  Top Layer w15: D1.1@1550,475.53 1626.91,552.44 C7.1@1635,552.44
HG: D2.2 HG.1 Q1.1 R5.2 | length 2058.6
  Top Layer w25: D2.2@1366.69,500 1382.44,515.75 R5.2@1382.44,571
  Bottom Layer w8: v5(1458,1650) 1490,1682 HG.1@1490,2100
  Bottom Layer w20: v5(1367.24,570) 1027,910.24 1027,1420.6 1058,1451.6 1058,1452 1256,1650 v5(1458,1650)
HO_N: C7.2 D3.1 L1.1 Q1.3 Q2.4 R4.2 R8.2 SW.1 U1.17 | length 2930.8
  Top Layer w14: v3(1650,608) 1664,608 1670.39,601.61 U1.17@1777.8,601.61
  Bottom Layer w8: v5(1425,1610) 1459,1610 1506,1657 1506,1770.33 1575.67,1840 SW.1@1740,1840
  Bottom Layer w10: v3(1650,608) 1664,608 1670.39,601.61 1734.1,601.61 1792,659.51 1792,744 1848,800 2037.56,800 2083,845.44 v2(2083,917.56)
  Bottom Layer w20: v5(1425,1610) 1256,1610 1055,1409 1055,921.84 1368.84,608 v3(1650,608)
  other v2: 1890,1423 1920,1423 1950,1423 1859,1430 1859,1460 1859,1490 1859,1520 1859,1550 1859,1580 1859,1610 1890,1618 1920,1618 1950,1618
  other v3: 1620,1483.86 1660,1483.86 1700,1483.86 1740,1483.86 1620,1523.86 1660,1523.86 1700,1523.86 1740,1523.86 1620,1563.86 1660,1563.86 1700,1563.86 1740,1563.86 1280,1575 1340,1575 1620,1603.86 1660,1603.86 1700,1603.86 1740,1603.86 1280,1685 1340,1685
HO_P: D2.1 R5.1 U1.18 | length 404.8
  Top Layer w14: v3(1680,570) 1686.02,576.02 U1.18@1777.8,576.02
  Top Layer w25: R5.1@1437.56,571 1437.56,515.75 D2.1@1453.31,500
  Bottom Layer w20: v5(1453,570) v3(1680,570)
LG: D4.2 Q2.1 Q3.2 R13.2 | length 145.2
  Bottom Layer w20: v5(1622,1310) 1629.4,1317.4 Q3.2@1672.6,1317.4
  Bottom Layer w25: D4.2@1520,1323.31 1535.75,1307.56 R13.2@1605,1307.56
LO: D4.1 LG.1 Q3.1 R13.1 U1.15 | length 1190.8
  Top Layer w14: v3(1720,652.8) U1.15@1777.8,652.8
  Bottom Layer w8: LG.1@1349.88,840 1500,840
  Bottom Layer w15: R13.1@1605,1252.44 1590,1237.44 1590,930 1500,840 1500,727.03 1574.23,652.8 v3(1720,652.8)
  Bottom Layer w20: R13.1@1605,1252.44 1614.84,1242.6 Q3.1@1672.6,1242.6
  Bottom Layer w25: D4.1@1520,1236.69 1535.75,1252.44 R13.1@1605,1252.44
NetC6_1: C6.1 R2.2 U1.20 | length 182.2
  Top Layer w15: R2.2@1722.44,380 C6.1@1722.44,430 1722.44,494.16 1753.12,524.84 U1.20@1777.8,524.84
NetC13_1: C13.1 R6.2 R7.2 | length 100
  Top Layer w20: R7.2@2402.44,860 R6.2@2402.44,960
NetC14_1: C14.1 R8.1 | length 82.8
  Top Layer w20: C14.1@2177.56,1119.56 2177.56,1194.41 R8.1@2183.15,1200
NetC19_2: C19.2 R9.2 | length 60
  Top Layer w15: R9.2@2247.56,700 C19.2@2247.56,760
NetCM_1: CM.1 R19.2 | length 218.5
  Bottom Layer w8: v2(2263,810) 2339.82,810 CM.1@2440,709.82
NetInput_1: Input.1 R12.1 R18.2 | length 448
  Top Layer w10: R12.1@2247.56,650 v2(2263,650)
  Bottom Layer w8: Input.1@2280,280 2347,347 v2(2347,450)
  Bottom Layer w10: v2(2263,650) 2347,566 v2(2347,450)
Q2-S: Q2.3 R14.2 Rs1.2 Rs2.2 | length 712.6
  Top Layer w15: v2(1769.76,1120.92) 1769.76,1161
  Top Layer w59: Rs1.2@1689.76,1161 1769.76,1161 Rs2.2@1849.76,1161
  Bottom Layer w8: v2(1547,794) 1558,783 1638,783 1664,809 1664,1007 1705.92,1048.92 1747.76,1048.92 1769.76,1070.92 v2(1769.76,1120.92)
  other v2: 1630,1190 1670,1190 1710,1190 1750,1190 1790,1190 1830,1190 1870,1190 1910,1190 1739.53,1237.28 1799.53,1237.28 1740,1315 1800,1315
RAMP: C8.1 R4.1 U1.11 | length 416.6
  Top Layer w10: U1.11@1777.8,755.16 1803.16,755.16 1848,800 2037.56,800 R4.1@2100,862.44 C8.1@2150,862.44
RES: C15.1 U1.3 | length 211.1
  Top Layer w10: U1.3@2002.2,576.02 2039.98,576.02 2065,551 2065,485 2100,450 C15.1@2122.44,450
RT: R11.2 U1.5 | length 160.7
  Top Layer w10: U1.5@2002.2,627.2 2059.8,627.2 2112,575 2112,560.44 R11.2@2122.44,550
SS: C16.1 SS.1 U1.4 | length 423.8
  Top Layer w10: U1.4@2002.2,601.61 2049.39,601.61 2085,566 2085,515 2100,500 v2(2108,500) C16.1@2122.44,500
  Bottom Layer w8: SS.1@2080,280 2080,472 v2(2108,500)
UVLO: R1.1 R3.2 U1.1 | length 147.1
  Top Layer w13: U1.1@2002.2,524.84 2007.56,519.49 R3.2@2007.56,430.01
  Top Layer w15: R1.1@2007.56,380 R3.2@2007.56,430.01
VADJ: PWM.1 R6.1 | length 344.2
  Bottom Layer w20: v3(2473,960) 2473,936.71 PWM.1@2699.88,709.82
VCC: C5.1 D1.2 U1.16 | length 254
  Top Layer w11: 1690.24,627.2 U1.16@1777.8,627.2
  Top Layer w12: C5.1@1670,647.44 1690.24,627.2
  Top Layer w15: D1.2@1550,604.47 1592.97,647.44 C5.1@1670,647.44
VIN: C1.1 C2.1 C3.1 C4.1 J1.1 Q1.4 R1.2 R2.1 Vin.1 | length 346.5
  Top Layer w20: R2.1@1777.56,380 R1.2@1952.44,380
  MidLayer2 w8: Vin.1@940,1213.15 1071.85,1213.15 v2(1100,1185)
  other v1: 255,1365 300,1365 345,1365 390,1365 710,1365 755,1365 255,1410 300,1410 345,1410 755,1410 255,1455 300,1455 255,1500 300,1500 255,1545 300,1545 255,1590 300,1590 255,1635 300,1635 345,1635 755,1635 255,1680 300,1680 345,1680 390,1680 710,1680 755,1680
  other v2: 1793,380 1130,1185 1160,1185 1230,1185 1260,1185 1290,1185 1360,1185 1390,1185 1420,1185 1490,1185 1520,1185 1550,1185
  other v3: 1340,1286.14 1380,1286.14 1420,1286.14 1460,1286.14 1340,1326.14 1380,1326.14 1420,1326.14 1460,1326.14 1340,1366.14 1380,1366.14 1420,1366.14 1460,1366.14 1340,1406.14 1380,1406.14 1420,1406.14 1460,1406.14
VOUT: C10.1 C11.1 C12.1 J3.1 L1.2 Output.1 R18.1 Vout.1 | length 304.8
  MidLayer2 w8: v2(2540,1330) Vout.1@2540,1437
  Bottom Layer w8: v3(2433,450) 2433,347 Output.1@2500,280
  other v1: 3295,1360 3340,1360 3660,1360 3705,1360 3750,1360 3795,1360 3295,1405 3705,1405 3750,1405 3795,1405 3750,1450 3795,1450 3750,1495 3795,1495 3750,1540 3795,1540 3750,1585 3795,1585 3295,1630 3705,1630 3750,1630 3795,1630 3295,1675 3340,1675 3660,1675 3705,1675 3750,1675 3795,1675
  other v2: 2506,1330 2574,1330 2596,1330 2630,1330 2664,1330 2310,1422 2340,1422 2370,1422 2401,1430 2401,1460 2401,1490 2401,1520 2401,1550 2401,1580 2401,1610 2310,1617 2340,1617 2370,1617
pads on no net: H1. H2. H3. H4. U1.7

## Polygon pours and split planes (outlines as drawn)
VOUT on Top Layer "Top Layer-Vout" (solid, pour order 12): 2150,1910 2150,1260 3035,1260 3165,1130 3900,1130 3900,1910
HO_N on Top Layer "Top Layer-SW" (solid, pour order 11): 2130,1950 2130,1100 1950,1100 1950,1235 1830,1355 1536,1355 1536,1680 1443,1680 1443,1560 1114.99,1560 1114.99,1950
VIN on Top Layer "Top Layer-Vin" (solid, pour order 13): 1100,1910 150,1910 150,1099.49 1600,1099.49 1600,1209 1520,1209 1520,1545 1100,1545
Q2-S on Top Layer "Top Layer-Q2-S" (solid, pour order 15): 1930,1100 1930,1230 1820,1340 1630,1340 1610,1320 1610,1120 1610,1100
GND on Top Layer "Top Layer-AGND" (solid, pour order 14): 1530,720 1820,720 1820,790 1990,790 2160,960 2270,960 2320,910 2320,500 2230,410 1660,410 1530,540
GND on Top Layer "Top Layer-PGND" (solid, pour order 16): 0,0 4050,0 4050,2360 0,2360
VOUT on MidLayer1 "MidLayer1-Vout" (solid, pour order 17): 4050,2360 2050,2360 2050,0 4050,0
VIN on MidLayer1 "MidLayer1-Vin" (solid, pour order 18): 2030,2360 0,2360 0,0 2030,0
GND on MidLayer2 "MidLayer2-GND" (solid, pour order 19): 0,0 4050,0 4050,2360 0,2360
GND on Bottom Layer "Bottom Layer-GND" (solid, pour order 20): 0,0 4050,0 4050,2360 0,2360

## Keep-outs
Keep-Out Layer:
  the board outline again, w10
  text ".Layer_Name" at 17,-1418.49 h60

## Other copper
Top Layer:
  rectangle net FB: 2130,632 2210,720
  pour cut-out: 1748.97,1120.92 1790.56,1120.92 1790.56,1096.55 1748.97,1096.55
  pour cut-out: 1748.97,960.92 1790.56,960.92 1790.56,936.55 1748.97,936.55
  pour cut-out: 150,1920 150,1099.49 1600,1100.02 1600,1209 1520,1209 1520,1545 1100,1545 1100,1910 150,1910 150,1920 1100,1920 1100,1960 2150,1960 2150,1260 2130,1260 2130,1950 1114.99,1950 1114.99,1560 1443,1560 1443,1680 1536,1680 1536,1209.96 1615,1209.96 1615,1100 1930,1100 1930,1230 1820,1340 1637,1340 1637,1209.96 1536,1209.96 1536,1355 1830,1355 1950,1235 1950,1100 2130,1100 2130,1260 3035,1260 3165,1130 3900,1130 3900,1910 2150,1910 2150,1920 3910,1920 3910,1120 3160,1120 3030,1250 2140,1250 2140,1090 140,1090 140,1920
  pour cut-out: 1820,800 1820,790 1990,790 2160,960 2270,960 2320,910 2320,500 2230,410 2146.19,410 2146.19,425.27 2138,425.27 2138,410 1660,410 1530,540 1530,720 1820,720 1820,800 1800,780 1540,780 1520,760 1520,535 1655,400 2230,400 2330,500 2330,910 2270,970 2155,970 1985,800
  pour cut-out: 1540,780 1540,720 1690,720 1720,690 1742,690 1742,722 1738,722 1680,780
  pour cut-out: 1820,690 1810.4,690 1810.4,737.57 1810,737.98 1820.43,737.98
  pour cut-out: 1769.76,1100.53 cw(c1769.76,1120.92) 1749.37,1120.92 cw(c1769.76,1120.92) 1769.76,1141.31 cw(c1769.76,1120.92) 1790.16,1120.92 cw(c1769.76,1120.92)
  pour cut-out: 1769.76,940.53 cw(c1769.76,960.92) 1749.37,960.92 cw(c1769.76,960.92) 1769.76,981.31 cw(c1769.76,960.92) 1790.16,960.92 cw(c1769.76,960.92)
  pour cut-out: 1740,1789.57 cw(c1740,1840) 1689.57,1840 cw(c1740,1840) 1740,1890.43 cw(c1740,1840) 1790.43,1840 cw(c1740,1840)
  pour cut-out: 2484.05,1073 ccw(c2540,1073) 2540,1017.05 ccw(c2540,1073) 2595.95,1073 ccw(c2540,1073) 2540,1128.95 ccw(c2540,1073)
  pour cut-out: 2484.05,1437 ccw(c2540,1437) 2540,1381.05 ccw(c2540,1437) 2595.95,1437 ccw(c2540,1437) 2540,1492.95 ccw(c2540,1437)
  pour cut-out: 1804.53,280 ccw(c1860,280) 1860,224.53 ccw(c1860,280) 1915.47,280 ccw(c1860,280) 1860,335.47 ccw(c1860,280)
  pour cut-out: 940,951.38 cw(c940,1006.85) 884.53,1006.85 cw(c940,1006.85) 940,1062.32 cw(c940,1006.85) 995.47,1006.85 cw(c940,1006.85)
  pour cut-out: 940,1157.68 cw(c940,1213.15) 884.53,1213.15 cw(c940,1213.15) 940,1268.62 cw(c940,1213.15) 995.47,1213.15 cw(c940,1213.15)
  text ".Layer_Name" at 17,-1418.49 h60
MidLayer1:
  pour cut-out: 2030,2360 2050,2360 2050,0 2030,0
  pour cut-out: 1769.76,940.53 cw(c1769.76,960.92) 1749.37,960.92 cw(c1769.76,960.92) 1769.76,981.31 cw(c1769.76,960.92) 1790.16,960.92 cw(c1769.76,960.92)
  pour cut-out: 2519.21,1330 ccw(c2540,1330) 2540,1309.21 ccw(c2540,1330) 2560.79,1330 ccw(c2540,1330) 2540,1350.79 ccw(c2540,1330)
  pour cut-out: 2484.05,1437 ccw(c2540,1437) 2540,1381.05 ccw(c2540,1437) 2595.95,1437 ccw(c2540,1437) 2540,1492.95 ccw(c2540,1437)
  pour cut-out: 1100,1164.61 cw(c1100,1185) 1079.61,1185 cw(c1100,1185) 1100,1205.39 cw(c1100,1185) 1120.39,1185 cw(c1100,1185)
  pour cut-out: 2444.53,280 ccw(c2500,280) 2500,224.53 ccw(c2500,280) 2555.47,280 ccw(c2500,280) 2500,335.47 ccw(c2500,280)
  pour cut-out: 940,1157.68 cw(c940,1213.15) 884.53,1213.15 cw(c940,1213.15) 940,1268.62 cw(c940,1213.15) 995.47,1213.15 cw(c940,1213.15)
  text ".Layer_Name" at 17,-1418.49 h60
MidLayer2:
  pour cut-out: 2484.05,1073 ccw(c2540,1073) 2540,1017.05 ccw(c2540,1073) 2595.95,1073 ccw(c2540,1073) 2540,1128.95 ccw(c2540,1073)
  pour cut-out: 2519.21,1180 ccw(c2540,1180) 2540,1159.21 ccw(c2540,1180) 2560.79,1180 ccw(c2540,1180) 2540,1200.79 ccw(c2540,1180)
  pour cut-out: 1100,1014.61 cw(c1100,1035) 1079.61,1035 cw(c1100,1035) 1100,1055.39 cw(c1100,1035) 1120.39,1035 cw(c1100,1035)
  pour cut-out: 1804.53,280 ccw(c1860,280) 1860,224.53 ccw(c1860,280) 1915.47,280 ccw(c1860,280) 1860,335.47 ccw(c1860,280)
  pour cut-out: 940,951.38 cw(c940,1006.85) 884.53,1006.85 cw(c940,1006.85) 940,1062.32 cw(c940,1006.85) 995.47,1006.85 cw(c940,1006.85)
  pour cut-out: 1769.76,935.43 cw(c1769.76,960.92) 1744.27,960.92 cw(c1769.76,960.92) 1769.76,986.41 cw(c1769.76,960.92) 1795.25,960.92 cw(c1769.76,960.92)
  pour cut-out: 1547,735.61 cw(c1547,756) 1526.61,756 cw(c1547,756) 1547,776.39 cw(c1547,756) 1567.39,756 cw(c1547,756)
  text ".Layer_Name" at 17,-1418.49 h60
Bottom Layer:
  pour cut-out: 1769.76,940.53 cw(c1769.76,960.92) 1749.37,960.92 cw(c1769.76,960.92) 1769.76,981.31 cw(c1769.76,960.92) 1790.16,960.92 cw(c1769.76,960.92)
  pour cut-out: 1100,1014.21 cw(c1100,1035) 1079.21,1035 cw(c1100,1035) 1100,1055.79 cw(c1100,1035) 1120.79,1035 cw(c1100,1035)
  pour cut-out: 2484.05,1073 ccw(c2540,1073) 2540,1017.05 ccw(c2540,1073) 2595.95,1073 ccw(c2540,1073) 2540,1128.95 ccw(c2540,1073)
  pour cut-out: 2519.21,1180 ccw(c2540,1180) 2540,1159.21 ccw(c2540,1180) 2560.79,1180 ccw(c2540,1180) 2540,1200.79 ccw(c2540,1180)
  pour cut-out: 1804.53,280 ccw(c1860,280) 1860,224.53 ccw(c1860,280) 1915.47,280 ccw(c1860,280) 1860,335.47 ccw(c1860,280)
  pour cut-out: 940,951.38 cw(c940,1006.85) 884.53,1006.85 cw(c940,1006.85) 940,1062.32 cw(c940,1006.85) 995.47,1006.85 cw(c940,1006.85)
  pour cut-out: 1870,659.68 ccw(c1890,659.68) 1890,639.68 ccw(c1890,659.68) 1910,659.68 ccw(c1890,659.68) 1890,679.68 ccw(c1890,659.68)
  pour cut-out: 1870,620.31 ccw(c1890,620.31) 1890,600.31 ccw(c1890,620.31) 1910,620.31 ccw(c1890,620.31) 1890,640.31 ccw(c1890,620.31)
  pour cut-out: 1909.37,580.94 ccw(c1929.37,580.94) 1929.37,560.94 ccw(c1929.37,580.94) 1949.37,580.94 ccw(c1929.37,580.94) 1929.37,600.94 ccw(c1929.37,580.94)
  pour cut-out: 1870,580.94 ccw(c1890,580.94) 1890,560.94 ccw(c1890,580.94) 1910,580.94 ccw(c1890,580.94) 1890,600.94 ccw(c1890,580.94)
  pour cut-out: 1830.63,580.94 ccw(c1850.63,580.94) 1850.63,560.94 ccw(c1850.63,580.94) 1870.63,580.94 ccw(c1850.63,580.94) 1850.63,600.94 ccw(c1850.63,580.94)
  pour cut-out: 1909.37,620.31 ccw(c1929.37,620.31) 1929.37,600.31 ccw(c1929.37,620.31) 1949.37,620.31 ccw(c1929.37,620.31) 1929.37,640.31 ccw(c1929.37,620.31)
  pour cut-out: 1830.63,620.31 ccw(c1850.63,620.31) 1850.63,600.31 ccw(c1850.63,620.31) 1870.63,620.31 ccw(c1850.63,620.31) 1850.63,640.31 ccw(c1850.63,620.31)
  pour cut-out: 1909.37,659.68 ccw(c1929.37,659.68) 1929.37,639.68 ccw(c1929.37,659.68) 1949.37,659.68 ccw(c1929.37,659.68) 1929.37,679.68 ccw(c1929.37,659.68)
  pour cut-out: 1830.63,659.68 ccw(c1850.63,659.68) 1850.63,639.68 ccw(c1850.63,659.68) 1870.63,659.68 ccw(c1850.63,659.68) 1850.63,679.68 ccw(c1850.63,659.68)
  pour cut-out: 1909.37,699.06 ccw(c1929.37,699.06) 1929.37,679.06 ccw(c1929.37,699.06) 1949.37,699.06 ccw(c1929.37,699.06) 1929.37,719.06 ccw(c1929.37,699.06)
  pour cut-out: 1870,699.06 ccw(c1890,699.06) 1890,679.06 ccw(c1890,699.06) 1910,699.06 ccw(c1890,699.06) 1890,719.06 ccw(c1890,699.06)
  pour cut-out: 1830.63,699.06 ccw(c1850.63,699.06) 1850.63,679.06 ccw(c1850.63,699.06) 1870.63,699.06 ccw(c1850.63,699.06) 1850.63,719.06 ccw(c1850.63,699.06)
  pour cut-out: 1547,735.61 cw(c1547,756) 1526.61,756 cw(c1547,756) 1547,776.39 cw(c1547,756) 1567.39,756 cw(c1547,756)
  text ".Layer_Name" at 17,-1418.49 h60

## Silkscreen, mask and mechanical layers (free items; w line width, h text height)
Top Overlay:
  text "LM25117" at 2681.5,1835 h60
  text ".CopyrightYear" at 617,123.52 h60
  text "TI" at 893,123.52 h60
  text "©" at 500,120 h105
  text ".Layer_Name" at 17,-1418.49 h60
Bottom Overlay:
  rectangle: 2468,2111.5 2768,2211.5
  text ".PCB_Rev" at 2938,2121.5 h60
  text ".PRJ_Number" at 3434,2121.5 h60
  text "-" at 2833,2111 h60
  text "MADE IN U.S." at 3120,120 h60
  text ".Layer_Name" at 17,-1418.49 h60
Top Paste:
  text ".Layer_Name" at 17,-1418.49 h60
Bottom Paste:
  text ".Layer_Name" at 17,-1418.49 h60
Top Solder:
  text ".Layer_Name" at 17,-1418.49 h60
  text ".Layer_Name" at 17,-1418.49 h60
Bottom Solder:
  text ".Layer_Name" at 17,-1418.49 h60
Drill Guide:
  text ".Layer_Name" at 17,-1418.49 h60
M1 Board Outline:
  the board outline again, w10
  text ".Layer_Name" at 17,-1418.49 h60
M2 Board Dimensions:
  rectangle: -435.5,-970.5 -60.5,-845.5
  rectangle: -560.5,-845.5 -435.5,-720.5
  lines w7: -560.5,-845.5 439.5,-845.5 ; -435.5,-970.5 -435.5,-720.5 ; -310.5,-970.5 -310.5,-720.5 ; -60.5,-970.5 -60.5,-720.5 ; 189.5,-970.5 189.5,-720.5 ; -560.5,-970.5 -560.5,-720.5 439.5,-720.5 439.5,-970.5 -560.5,-970.5
  lines w10: -560.5,-1035.5 -560.5,-1015.5 ; -500.5,-1045.5 -560.5,-1025.5 ; -500.5,-1005.5 -560.5,-1025.5 ; -336.42,-1025.5 -560.5,-1025.5 ; 215.42,-1025.5 439.5,-1025.5 ; 379.5,-1045.5 439.5,-1025.5 ; 379.5,-1005.5 439.5,-1025.5 ; 439.5,-1035.5 439.5,-1015.5
  text "1000 (mil)" at -326.42,-1061.49 h60
  text ".Layer_Name" at 17,-1418.49 h60
M3 3D STEP Top:
  text ".Layer_Name" at 17,-1418.49 h60
M4 3D STEP Bottom:
  text ".Layer_Name" at 17,-1418.49 h60
M5 Assembly Top:
  lines w7: 4579,-449.5 5704,-449.5 ; 4579,-327 5701.5,-327 ; 4894,-569.5 4894,-207 ; 5279,-569.5 4579,-569.5 ; 5279,-207 4579,-207 ; 4579,-569.5 4579,-207 ; 4579,-569.5 5704,-569.5 5704,-207 4579,-207
  lines w10: -852,-1490.17 5748,-1490.17 ; -852,-1286.83 5750,-1286.83 ; -852,-1083.5 -852,-1693.5 3153,-1693.5 5750,-1693.5 5750,-1083.5 -851.5,-1083.5 -851.5,-1693.5 724,-1693.5 ; 1613,-1693.5 1613,-1083.5 ; 2880,-1286.83 2880,-1083.5 ; 3720,-1286.83 3720,-1083.5 ; 4342,-1700 4342,-1497.17
  text "TABLE 1" at 4966.5,-172 h40
  text "Variant" at 4604,-282 h40
  text "Label text" at 5039,-282 h40
  text "001" at 4671.5,-402 h40
  text "COMPONENTS MARKED 'DNP' SHOULD NOT BE POPULATED." at 593.5,-878.5 h60
  text "ASSEMBLY VARIANT:" at 593,-994 h60
  text ".VariantName" at 1629,-994 h60
  text "PCB VIEWED FROM TOP SIDE" at -788.5,-1215.67 h60
  text "BOARD #:" at 1688,-1215.67 h60
  text ".PRJ_Number" at 2233.5,-1215.67 h60
  text "REV:" at 3078,-1215.67 h60
  text ".PCB_Rev" at 3369.5,-1215.67 h60
  text "SVN REV:" at 3916,-1215.67 h60
  text ".VersionControl_RevNumber" at 4422,-1215.67 h60
  text "IGNORE ->" at -788.5,-1418.49 h60
  text "PLOT NAME =" at -788.5,-1624.34 h60
  text ".plot_File_Name" at 17,-1624.34 h60
  text "GENERATED    :" at 1690,-1624.34 h60
  text ".Print_Date" at 2559.5,-1624.34 h60
  text ".Print_Time" at 3288.5,-1624.34 h60
  text "TEXAS INSTRUMENTS" at 4553,-1624.34 h60
M6 Assembly Bottom:
  lines w10: -852.5,-1287.33 5749.5,-1287.33 ; -850.5,-1490.67 5749.5,-1490.67 ; 555.5,-1700.5 555.5,-1497.67 ; 1177.5,-1287.33 1177.5,-1084 ; 2017.5,-1287.33 2017.5,-1084 ; 3284.5,-1694 3284.5,-1084 ; 4173.5,-1694 5749,-1694 5749,-1084 -852.5,-1084 -852.5,-1694 1744.5,-1694 5749.5,-1694 5749.5,-1084
  text "COMPONENTS MARKED 'DNP' SHOULD NOT BE POPULATED." at 5542,-878 h60
  text ".VariantName" at 4498,-994 h60
  text "ASSEMBLY VARIANT:" at 5537,-994 h60
  text ".VersionControl_RevNumber" at 475.5,-1216.17 h60
  text "SVN REV:" at 981.5,-1216.17 h60
  text ".PCB_Rev" at 1528,-1216.17 h60
  text "REV:" at 1819.5,-1216.17 h60
  text ".PRJ_Number" at 2664,-1216.17 h60
  text "BOARD #:" at 3209.5,-1216.17 h60
  text "PCB VIEWED FROM BOTTOM SIDE" at 5686,-1216.17 h60
  text "IGNORE ->" at 1987.85,-1418.49 h60
  text "TEXAS INSTRUMENTS" at 344.5,-1624.84 h60
  text ".Print_Time" at 1609,-1624.84 h60
  text ".Print_Date" at 2338,-1624.84 h60
  text "GENERATED    :" at 3207.5,-1624.84 h60
  text ".plot_File_Name" at 4880.5,-1624.84 h60
  text "PLOT NAME =" at 5686,-1624.84 h60
M9 Title Sheet:
  drawing of 57 lines, arcs and shapes, not listed
  text "1" at 179.84,7476.5 h70
  text "2" at 2675.5,7476.5 h70
  text "3" at 5164.84,7476.5 h70
  text "4" at 7671.51,7476.5 h70
  text "5" at 10170.5,7476.5 h70
  text "6" at 12675.5,7476.5 h70
  text "A" at -976.5,6333.5 h70
  text "A" at 13823.5,6333.5 h70
  text "B" at -976.5,3953.5 h70
  text "B" at 13823.5,3953.5 h70
  text "C" at -976.5,1578.5 h70
  text "C" at 13823.5,1578.5 h70
  text "PROJECT TITLE:" at 10783.5,-282.5 h45
  text ".PRJ_Title" at 10833.5,-415.83 h70
  text "DESIGNED FOR:" at 10783.5,-583.5 h45
  text ".PRJ_Customer" at 10833.5,-723.5 h70
  text "D" at -976.5,-791.5 h70
  text "D" at 13823.5,-791.5 h70
  text "FILE NAME:" at 10783.5,-883.5 h45
  text ".PCB_File_Name_No_Path" at 10833.5,-1003.5 h70
  text "Texas Instruments (TI) and/or its licensors do not warrant the accuracy or completeness of this specification" at 5814,-1165.34 h45
  text "ENGINEER:" at 10783.5,-1173.5 h45
  text "LAYOUT BY:" at 12288.5,-1173.5 h45
  text "or any information contained therein. TI and/or its licensors do not warrant that this design will meet" at 5769.01,-1278 h45
  text ".PRJ_Engineer" at 10833.5,-1328.49 h70
  text ".PCB_Layout" at 12339,-1328.49 h70
  text "the specifications, will be suitable for your application or fit for any particular purpose, or will operate in" at 5769.01,-1390.67 h45
  text ".Layer_Name" at 17,-1418.49 h60
  text "ALTIUM DESIGNER VERSION:" at 12288.5,-1483.5 h45
  text "an implementation. TI and/or its licensors do not warrant that the design is production worthy. You should" at 5769.01,-1503.33 h45
  text "completely validate and test your design implementation to confirm the system functionality for your application." at 5814,-1616 h45
  text ".print_Scale" at 10833.5,-1616.83 h70
  text ".Application_BuildNumber" at 12339,-1616.83 h70
  text "1" at 179.84,-1823.5 h70
  text "2" at 2675.5,-1823.5 h70
  text "3" at 5164.84,-1823.5 h70
  text "4" at 7671.51,-1823.5 h70
  text "5" at 10170.5,-1823.5 h70
  text "6" at 12675.5,-1823.5 h70
M10 Fab Notes:
  drawing of 212 lines, arcs and shapes, not listed
  text "DESIGN INFORMATION" at 11821.02,6250 h60
  text "(REFER ALSO ARRAY/PANEL PROFILING INFORMATION)" at 11459.46,6088.29 h60
  text "BOARD SIZE" at 10773.46,6084 h60
  text "2360MIL" at 11235.78,5956.18 h60
  text "X" at 11741.46,5956.18 h60
  text "4050MIL" at 11972.78,5956.18 h60
  text "4" at 12276,5765 h60
  text "Number of Layers :" at 11176.46,5759 h60
  text "MIN. TRACK WIDTH:" at 11176.46,5620 h60
  text "8" at 12272.7,5620 h60
  text "MIL" at 12427.46,5620 h60
  text "MIN. CLEARANCE:" at 11176.46,5488 h60
  text "8" at 12272.7,5488 h60
  text "MIL" at 12427.46,5488 h60
  text "MIN. VIA PAD SIZE:" at 11176.46,5356 h60
  text "20" at 12242.71,5356 h60
  text "MIL" at 12427.46,5356 h60
  text "0.05mm (2MIL)" at 11871.46,5214.29 h60
  text "MINIMUM ANNULAR RING" at 10847.23,5210 h60
  text "EXTERNAL" at 12579.46,5210 h60
  text "PER" at 11047.23,5092 h60
  text "IPC-D-275 CLASS 2 LEVEL C" at 11267.23,5092 h60
  text "MIL, HOLES" at 12755.46,4979.71 h60
  text "+/-" at 12363,4979 h60
  text "+/-" at 13217,4979 h60
  text "REGISTRATION TOLERANCES:" at 10847.23,4974 h60
  text "METAL" at 12047,4974 h60
  text "5" at 12623.2,4974 h60
  text "3" at 13456.2,4974 h60
  text "MIL" at 13572.46,4974 h60
  text "MATERIAL:" at 10772.46,4764.54 h60
  text "FR-4 High Tg" at 11758.9,4624.21 h60
  text "FR-408" at 11193.46,4615.64 h60
  text "X" at 11605.46,4615.64 h60
  text "OTHER" at 12681.46,4615.64 h60
  text "62 MIL (1.6mm) +/-10%" at 11513.56,4452.92 h60
  text "THICKNESS:" at 10847.23,4448.64 h60
  text "X" at 11385.4,4448.64 h60
  text "OTHER" at 12798.46,4448.64 h60
  text "TOLERANCE:" at 10847.23,4290.64 h60
  text "X" at 11686.53,4290.64 h60
  text "ANSI IPC-6012 TYPE 3 CLASS 2" at 11873.48,4290.64 h60
  text "OTHER +/-" at 11873.46,4134.64 h60
  text "BOW & TWIST:" at 10847.23,3977.64 h60
  text "X" at 11686.53,3977.64 h60
  text "ANSI IPC-6012 TYPE 3 CLASS 2" at 11873.48,3977.64 h60
  text "OTHER +/-" at 11873.46,3819.13 h60
  text "COPPER THICKNESS (FINISHED):" at 10772.46,3683.64 h60
  text "1.4MIL (1oz)" at 11652.46,3530.92 h60
  text "2MIL (1.4oz)" at 12419.46,3530.92 h60
  text "2.8MIL (2oz)" at 13146.46,3530.92 h60
  text "OUTER:" at 11129.46,3526.64 h60
  text "X" at 11524,3526 h60
  text "1.4MIL (1oz)" at 11652.46,3373.92 h60
  text "2.8MIL (2oz)" at 12419.46,3373.92 h60
  text "N/A" at 13146,3374.29 h60
  text "INNER SIGNAL:" at 10840.38,3369.64 h60
  text "X" at 11525.42,3369.64 h60
  text "DRILLING:" at 10772.46,3230.64 h60
  text "REFERENCE:" at 10847.23,3113.64 h60
  text "X" at 11495.46,3113.64 h60
  text "AS SHOWN" at 11682.46,3113.64 h60
  text "X" at 12396.46,3113.64 h60
  text "NC_DRILL FILES" at 12533.46,3113.64 h60
  text "PTH MIN COPPER THICKNESS:" at 10847.23,2955.64 h60
  text "X" at 12197.46,2955.64 h60
  text "1MIL" at 12334.46,2955.64 h60
  text "OTHER" at 12831.46,2955.64 h60
  text "BOARD FINISH:" at 10772.46,2796.64 h60
  text "SILKSCREEN:" at 10927.68,2678.64 h60
  text "X" at 11876.46,2678.64 h60
  text "TOP" at 12002.46,2678.64 h60
  text "X" at 12386.46,2678.64 h60
  text "BOTTOM" at 12513.46,2678.64 h60
  text "SILKSCREEN COLOR:" at 10927.68,2511.64 h60
  text "X" at 11875.42,2511.64 h60
  text "WHITE" at 12002.46,2511.64 h60
  text "OTHER" at 12513.46,2511.64 h60
  text "SOLDER RESIST COLOR:" at 10927.68,2341.64 h60
  text "X" at 11495.42,2182.44 h60
  text "GREEN" at 11622.46,2182.44 h60
  text "BLUE" at 12213.46,2182.44 h60
  text "OTHER" at 12751.46,2182.44 h60
  text "IMMERSION GOLD (ENIG)" at 11833.46,1993.92 h60
  text "ENEPIG" at 13171,1990.64 h60
  text "SURFACE FINISH:" at 10772.46,1989.64 h60
  text "IMM. TIN/SILVER OR EQUIV" at 11102,1832.64 h60
  text "OTHER" at 12533.46,1832.64 h60
  text "X" at 10936,1827 h60
  text "X" at 11643,1656 h60
  text "ARRAY/PANEL:" at 10772.46,1653.64 h60
  text "CUT AND TRIM PER MECH LAYER 1" at 11833.46,1649.35 h60
  text "N.C. ROUTE" at 11833.46,1497.64 h60
  text "V. SCORE" at 12699.46,1497.64 h60
  text "CERTIFICATION:" at 10772.46,1360.64 h60
  text "MATERIALS AND WORKMANSHIP FOR ALL PCBS" at 11497.46,1360.64 h60
  text "TO MEET OR EXCEED THE REQUIREMENTS OF:" at 11497.46,1262.64 h60
  text "X" at 11123.96,1126.13 h60
  text "ANSI IPC-A-600F CLASS ->" at 11262.96,1126.13 h60
  text "X" at 12902.02,1126.13 h60
  text "2" at 13020.96,1126.14 h60
  text "1" at 12705.96,1124.64 h60
  text "3" at 13374.96,1124.64 h60
  text "X" at 11126.02,966.64 h60
  text "UL 94V-0" at 11262.96,966.64 h60
  text "X" at 11938.02,966.64 h60
  text "RoHS" at 12074.96,966.64 h60
  text "OTHER" at 12719.36,966.64 h60
  text "PER ORDER" at 13116.42,966.64 h60
  text "ADDITIONAL REQUIREMENTS:" at 10772.46,825.64 h60
  text "MICROSECTION:" at 10847.23,710.64 h60
  text "YES" at 11752.96,710.64 h60
  text "REQUIRED" at 12614.46,554.49 h60
  text "BARE BOARD ELEC. TEST:" at 10847.23,551.64 h60
  text "NONE" at 12152.96,551.64 h60
  text "PER ORDER" at 13206.46,551.64 h60
  text "X" at 12030,546 h60
  text "MANUFACTURER'S UL:" at 10847.23,394.64 h60
  text "RAIL" at 12012.96,390.35 h60
  text "METAL" at 12504.77,390.35 h60
  text "X" at 12880,390 h60
  text "SILK" at 13016.46,390.35 h60
  text ".Layer_Name" at 17,-1418.49 h60
M11 Gerber Information:
  lines w10: -852,-1490.17 5748,-1490.17 ; -852,-1286.83 5750,-1286.83 ; -852,-1083.5 -852,-1693.5 3153,-1693.5 5750,-1693.5 5750,-1083.5 -851.5,-1083.5 -851.5,-1693.5 724,-1693.5 ; 1613,-1693.5 1613,-1083.5 ; 2880,-1286.83 2880,-1083.5 ; 3720,-1286.83 3720,-1083.5 ; 4342,-1700 4342,-1497.17
  text "ALL ARTWORK VIEWED FROM TOP SIDE" at -788.5,-1215.67 h60
  text "BOARD #:" at 1688,-1215.67 h60
  text ".PRJ_Number" at 2233.5,-1215.67 h60
  text "REV:" at 3078,-1215.67 h60
  text ".PCB_Rev" at 3369.5,-1215.67 h60
  text "SVN REV:" at 3916,-1215.67 h60
  text ".VersionControl_RevNumber" at 4422,-1215.67 h60
  text "LAYER NAME =" at -788.5,-1418.49 h60
  text "PLOT NAME =" at -788.5,-1624.34 h60
  text ".plot_File_Name" at 17,-1624.34 h60
  text "GENERATED    :" at 1690,-1624.34 h60
  text ".Print_Date" at 2559.5,-1624.34 h60
  text ".Print_Time" at 3288.5,-1624.34 h60
  text "TEXAS INSTRUMENTS" at 4553,-1624.34 h60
